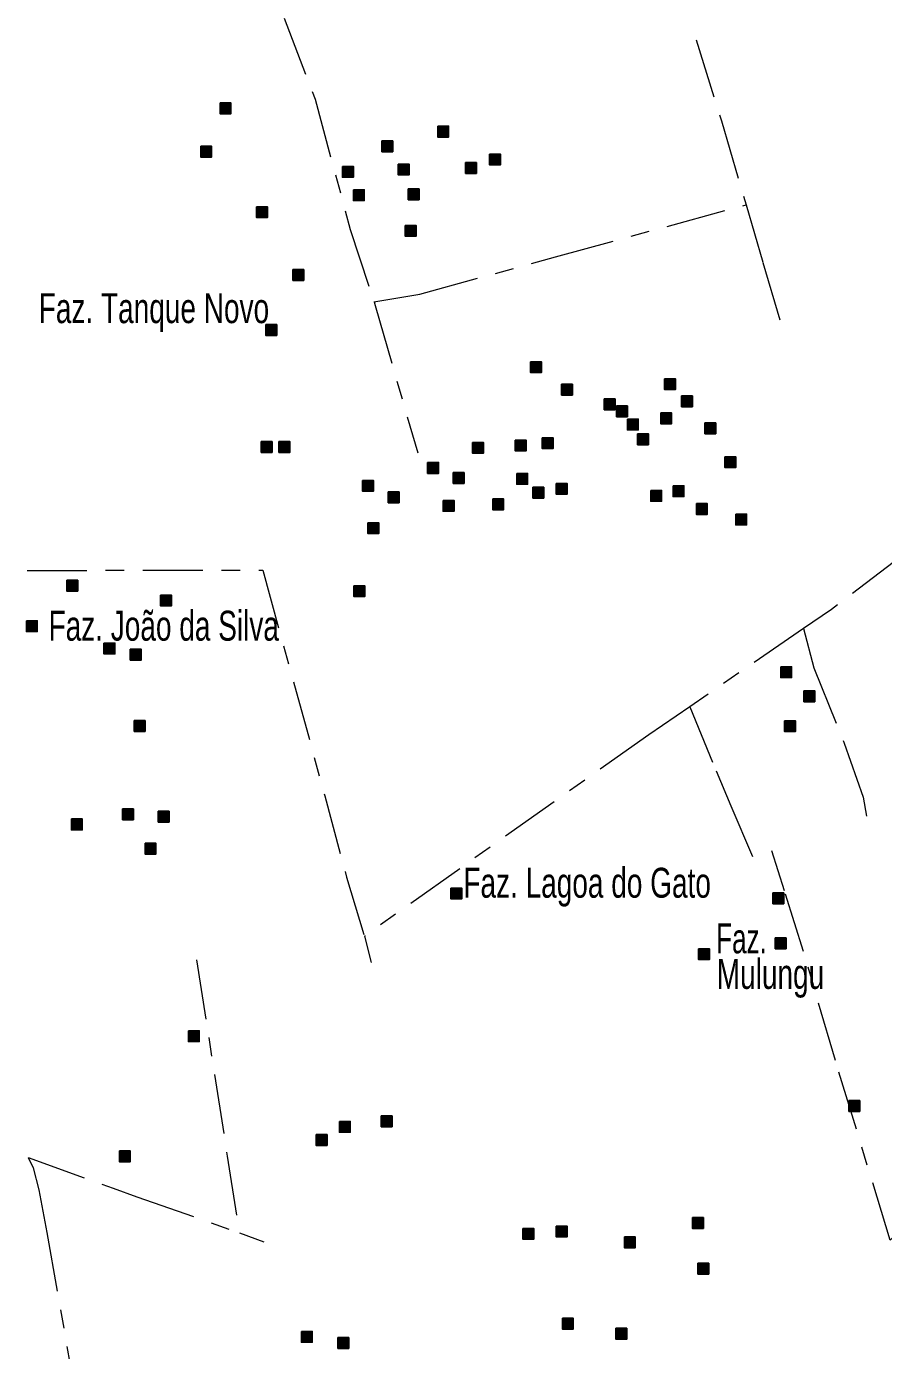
# Model space of a CAD drawing. Extents: x 445.4 to 500, y 8728.7 to 8784.
# Drawn here: x 445.42 to 450, y 8750.72 to 8757.8 of the extents above; entities that cross this region are included whole.
import ezdxf
from ezdxf.enums import TextEntityAlignment as Align

# ---------------------------------------------------------------- set-up
doc = ezdxf.new("R2010")
doc.units = 0
doc.header["$LTSCALE"] = 0.064
doc.linetypes.add('DOT_DASHED', pattern=[7.7, 5, -1.2, 0.3, -1.2])
doc.layers.add('2', color=7, linetype='Continuous', lineweight=25)
doc.layers.add('22', color=7, linetype='DOT_DASHED', lineweight=13)
doc.layers.add('61', color=7, linetype='Continuous')

msp = doc.modelspace()

# ---------------------------------------------------------------- hatches: boundary and pattern name
at = {"layer": '2'}
for points in [[(446.457, 8757.3873), (446.515, 8757.3873), (446.515, 8757.3293), (446.457, 8757.3293)], [(447.6207, 8757.263), (447.6787, 8757.263), (447.6787, 8757.205), (447.6207, 8757.205)], [(446.3534, 8757.1552), (446.4114, 8757.1552), (446.4114, 8757.0972), (446.3534, 8757.0972)], [(447.3225, 8757.1842), (447.3805, 8757.1842), (447.3805, 8757.1262), (447.3225, 8757.1262)], [(447.4095, 8757.0599), (447.4675, 8757.0599), (447.4675, 8757.0019), (447.4095, 8757.0019)], [(447.7698, 8757.0682), (447.8278, 8757.0682), (447.8278, 8757.0102), (447.7698, 8757.0102)], [(447.8981, 8757.1138), (447.9561, 8757.1138), (447.9561, 8757.0558), (447.8981, 8757.0558)], [(447.1113, 8757.0475), (447.1693, 8757.0475), (447.1693, 8756.9895), (447.1113, 8756.9895)], [(447.1693, 8756.9232), (447.2273, 8756.9232), (447.2273, 8756.8652), (447.1693, 8756.8652)], [(447.4633, 8756.9273), (447.5213, 8756.9273), (447.5213, 8756.8693), (447.4633, 8756.8693)], [(446.6516, 8756.832), (446.7096, 8756.832), (446.7096, 8756.774), (446.6516, 8756.774)], [(447.4467, 8756.7326), (447.5047, 8756.7326), (447.5047, 8756.6746), (447.4467, 8756.6746)], [(446.8462, 8756.4964), (446.9042, 8756.4964), (446.9042, 8756.4384), (446.8462, 8756.4384)], [(446.7013, 8756.2022), (446.7593, 8756.2022), (446.7593, 8756.1442), (446.7013, 8756.1442)], [(448.1176, 8756.0032), (448.1756, 8756.0032), (448.1756, 8755.9452), (448.1176, 8755.9452)], [(448.2833, 8755.8831), (448.3413, 8755.8831), (448.3413, 8755.8251), (448.2833, 8755.8251)], [(448.8341, 8755.9121), (448.8921, 8755.9121), (448.8921, 8755.8541), (448.8341, 8755.8541)], [(448.5111, 8755.8043), (448.5691, 8755.8043), (448.5691, 8755.7463), (448.5111, 8755.7463)], [(448.9252, 8755.8209), (448.9832, 8755.8209), (448.9832, 8755.7629), (448.9252, 8755.7629)], [(448.5773, 8755.7671), (448.6353, 8755.7671), (448.6353, 8755.7091), (448.5773, 8755.7091)], [(448.8134, 8755.7298), (448.8714, 8755.7298), (448.8714, 8755.6718), (448.8134, 8755.6718)], [(448.6353, 8755.6966), (448.6933, 8755.6966), (448.6933, 8755.6386), (448.6353, 8755.6386)], [(449.0494, 8755.6759), (449.1074, 8755.6759), (449.1074, 8755.6179), (449.0494, 8755.6179)], [(446.6765, 8755.5764), (446.7345, 8755.5764), (446.7345, 8755.5184), (446.6765, 8755.5184)], [(446.7717, 8755.5764), (446.8297, 8755.5764), (446.8297, 8755.5184), (446.7717, 8755.5184)], [(447.807, 8755.5723), (447.865, 8755.5723), (447.865, 8755.5143), (447.807, 8755.5143)], [(448.0348, 8755.5847), (448.0928, 8755.5847), (448.0928, 8755.5267), (448.0348, 8755.5267)], [(448.1798, 8755.5972), (448.2378, 8755.5972), (448.2378, 8755.5392), (448.1798, 8755.5392)], [(448.6891, 8755.6179), (448.7471, 8755.6179), (448.7471, 8755.5599), (448.6891, 8755.5599)], [(449.1568, 8755.4951), (449.2148, 8755.4951), (449.2148, 8755.4371), (449.1568, 8755.4371)], [(447.5668, 8755.4646), (447.6248, 8755.4646), (447.6248, 8755.4066), (447.5668, 8755.4066)], [(447.219, 8755.3692), (447.277, 8755.3692), (447.277, 8755.3112), (447.219, 8755.3112)], [(447.7035, 8755.4107), (447.7615, 8755.4107), (447.7615, 8755.3527), (447.7035, 8755.3527)], [(448.0431, 8755.4065), (448.1011, 8755.4065), (448.1011, 8755.3485), (448.0431, 8755.3485)], [(448.2543, 8755.3527), (448.3123, 8755.3527), (448.3123, 8755.2947), (448.2543, 8755.2947)], [(447.3556, 8755.3071), (447.4136, 8755.3071), (447.4136, 8755.2491), (447.3556, 8755.2491)], [(448.1301, 8755.332), (448.1881, 8755.332), (448.1881, 8755.274), (448.1301, 8755.274)], [(448.7595, 8755.3154), (448.8175, 8755.3154), (448.8175, 8755.2574), (448.7595, 8755.2574)], [(448.8796, 8755.3402), (448.9376, 8755.3402), (448.9376, 8755.2822), (448.8796, 8755.2822)], [(447.6497, 8755.2615), (447.7077, 8755.2615), (447.7077, 8755.2035), (447.6497, 8755.2035)], [(447.9147, 8755.2698), (447.9727, 8755.2698), (447.9727, 8755.2118), (447.9147, 8755.2118)], [(449.0039, 8755.2449), (449.0619, 8755.2449), (449.0619, 8755.1869), (449.0039, 8755.1869)], [(447.2473, 8755.1427), (447.3053, 8755.1427), (447.3053, 8755.0847), (447.2473, 8755.0847)], [(449.2148, 8755.1885), (449.2728, 8755.1885), (449.2728, 8755.1305), (449.2148, 8755.1305)], [(445.637, 8754.8347), (445.695, 8754.8347), (445.695, 8754.7767), (445.637, 8754.7767)], [(447.172, 8754.8057), (447.23, 8754.8057), (447.23, 8754.7477), (447.172, 8754.7477)], [(446.1381, 8754.756), (446.1961, 8754.756), (446.1961, 8754.698), (446.1381, 8754.698)], [(445.4212, 8754.6186), (445.4792, 8754.6186), (445.4792, 8754.5606), (445.4212, 8754.5606)], [(445.8358, 8754.499), (445.8938, 8754.499), (445.8938, 8754.441), (445.8358, 8754.441)], [(445.9766, 8754.4659), (446.0346, 8754.4659), (446.0346, 8754.4079), (445.9766, 8754.4079)], [(449.455, 8754.3722), (449.513, 8754.3722), (449.513, 8754.3142), (449.455, 8754.3142)], [(449.5793, 8754.2437), (449.6373, 8754.2437), (449.6373, 8754.1857), (449.5793, 8754.1857)], [(445.9973, 8754.0847), (446.0553, 8754.0847), (446.0553, 8754.0267), (445.9973, 8754.0267)], [(449.4757, 8754.0835), (449.5337, 8754.0835), (449.5337, 8754.0255), (449.4757, 8754.0255)], [(445.9352, 8753.6123), (445.9932, 8753.6123), (445.9932, 8753.5543), (445.9352, 8753.5543)], [(446.1257, 8753.5998), (446.1837, 8753.5998), (446.1837, 8753.5418), (446.1257, 8753.5418)], [(445.6618, 8753.5584), (445.7198, 8753.5584), (445.7198, 8753.5004), (445.6618, 8753.5004)], [(446.0553, 8753.4291), (446.1133, 8753.4291), (446.1133, 8753.3711), (446.0553, 8753.3711)], [(447.6911, 8753.1888), (447.7491, 8753.1888), (447.7491, 8753.1308), (447.6911, 8753.1308)], [(449.4136, 8753.163), (449.4716, 8753.163), (449.4716, 8753.105), (449.4136, 8753.105)], [(449.426, 8752.9227), (449.484, 8752.9227), (449.484, 8752.8647), (449.426, 8752.8647)], [(449.016, 8752.8646), (449.074, 8752.8646), (449.074, 8752.8066), (449.016, 8752.8066)], [(446.2872, 8752.4263), (446.3452, 8752.4263), (446.3452, 8752.3683), (446.2872, 8752.3683)], [(449.8195, 8752.0525), (449.8775, 8752.0525), (449.8775, 8751.9945), (449.8195, 8751.9945)], [(447.3184, 8751.9705), (447.3764, 8751.9705), (447.3764, 8751.9125), (447.3184, 8751.9125)], [(447.0947, 8751.9415), (447.1527, 8751.9415), (447.1527, 8751.8835), (447.0947, 8751.8835)], [(446.9705, 8751.871), (447.0285, 8751.871), (447.0285, 8751.813), (446.9705, 8751.813)], [(445.9186, 8751.784), (445.9766, 8751.784), (445.9766, 8751.726), (445.9186, 8751.726)], [(448.9832, 8751.4276), (449.0412, 8751.4276), (449.0412, 8751.3696), (448.9832, 8751.3696)], [(448.0762, 8751.3696), (448.1342, 8751.3696), (448.1342, 8751.3116), (448.0762, 8751.3116)], [(448.2543, 8751.3821), (448.3123, 8751.3821), (448.3123, 8751.3241), (448.2543, 8751.3241)], [(448.6187, 8751.3241), (448.6767, 8751.3241), (448.6767, 8751.2661), (448.6187, 8751.2661)], [(449.0122, 8751.1832), (449.0702, 8751.1832), (449.0702, 8751.1252), (449.0122, 8751.1252)], [(448.2874, 8750.889), (448.3454, 8750.889), (448.3454, 8750.831), (448.2874, 8750.831)], [(448.5732, 8750.8351), (448.6312, 8750.8351), (448.6312, 8750.7771), (448.5732, 8750.7771)], [(446.8918, 8750.8185), (446.9498, 8750.8185), (446.9498, 8750.7605), (446.8918, 8750.7605)], [(447.0864, 8750.7854), (447.1444, 8750.7854), (447.1444, 8750.7274), (447.0864, 8750.7274)]]:
    msp.add_hatch(color=256, dxfattribs=at).paths.add_polyline_path(points)

# ---------------------------------------------------------------- linework, layer by layer
for points in [[(446.457, 8757.3873), (446.515, 8757.3873), (446.515, 8757.3293), (446.457, 8757.3293)], [(447.6207, 8757.263), (447.6787, 8757.263), (447.6787, 8757.205), (447.6207, 8757.205)], [(446.3534, 8757.1552), (446.4114, 8757.1552), (446.4114, 8757.0972), (446.3534, 8757.0972)], [(447.3225, 8757.1842), (447.3805, 8757.1842), (447.3805, 8757.1262), (447.3225, 8757.1262)], [(447.4095, 8757.0599), (447.4675, 8757.0599), (447.4675, 8757.0019), (447.4095, 8757.0019)], [(447.7698, 8757.0682), (447.8278, 8757.0682), (447.8278, 8757.0102), (447.7698, 8757.0102)], [(447.8981, 8757.1138), (447.9561, 8757.1138), (447.9561, 8757.0558), (447.8981, 8757.0558)], [(447.1113, 8757.0475), (447.1693, 8757.0475), (447.1693, 8756.9895), (447.1113, 8756.9895)], [(447.1693, 8756.9232), (447.2273, 8756.9232), (447.2273, 8756.8652), (447.1693, 8756.8652)], [(447.4633, 8756.9273), (447.5213, 8756.9273), (447.5213, 8756.8693), (447.4633, 8756.8693)], [(446.6516, 8756.832), (446.7096, 8756.832), (446.7096, 8756.774), (446.6516, 8756.774)], [(447.4467, 8756.7326), (447.5047, 8756.7326), (447.5047, 8756.6746), (447.4467, 8756.6746)], [(446.8462, 8756.4964), (446.9042, 8756.4964), (446.9042, 8756.4384), (446.8462, 8756.4384)], [(446.7013, 8756.2022), (446.7593, 8756.2022), (446.7593, 8756.1442), (446.7013, 8756.1442)], [(448.1176, 8756.0032), (448.1756, 8756.0032), (448.1756, 8755.9452), (448.1176, 8755.9452)], [(448.2833, 8755.8831), (448.3413, 8755.8831), (448.3413, 8755.8251), (448.2833, 8755.8251)], [(448.8341, 8755.9121), (448.8921, 8755.9121), (448.8921, 8755.8541), (448.8341, 8755.8541)], [(448.5111, 8755.8043), (448.5691, 8755.8043), (448.5691, 8755.7463), (448.5111, 8755.7463)], [(448.9252, 8755.8209), (448.9832, 8755.8209), (448.9832, 8755.7629), (448.9252, 8755.7629)], [(448.5773, 8755.7671), (448.6353, 8755.7671), (448.6353, 8755.7091), (448.5773, 8755.7091)], [(448.8134, 8755.7298), (448.8714, 8755.7298), (448.8714, 8755.6718), (448.8134, 8755.6718)], [(448.6353, 8755.6966), (448.6933, 8755.6966), (448.6933, 8755.6386), (448.6353, 8755.6386)], [(449.0494, 8755.6759), (449.1074, 8755.6759), (449.1074, 8755.6179), (449.0494, 8755.6179)], [(446.6765, 8755.5764), (446.7345, 8755.5764), (446.7345, 8755.5184), (446.6765, 8755.5184)], [(446.7717, 8755.5764), (446.8297, 8755.5764), (446.8297, 8755.5184), (446.7717, 8755.5184)], [(447.807, 8755.5723), (447.865, 8755.5723), (447.865, 8755.5143), (447.807, 8755.5143)], [(448.0348, 8755.5847), (448.0928, 8755.5847), (448.0928, 8755.5267), (448.0348, 8755.5267)], [(448.1798, 8755.5972), (448.2378, 8755.5972), (448.2378, 8755.5392), (448.1798, 8755.5392)], [(448.6891, 8755.6179), (448.7471, 8755.6179), (448.7471, 8755.5599), (448.6891, 8755.5599)], [(449.1568, 8755.4951), (449.2148, 8755.4951), (449.2148, 8755.4371), (449.1568, 8755.4371)], [(447.5668, 8755.4646), (447.6248, 8755.4646), (447.6248, 8755.4066), (447.5668, 8755.4066)], [(447.219, 8755.3692), (447.277, 8755.3692), (447.277, 8755.3112), (447.219, 8755.3112)], [(447.7035, 8755.4107), (447.7615, 8755.4107), (447.7615, 8755.3527), (447.7035, 8755.3527)], [(448.0431, 8755.4065), (448.1011, 8755.4065), (448.1011, 8755.3485), (448.0431, 8755.3485)], [(448.2543, 8755.3527), (448.3123, 8755.3527), (448.3123, 8755.2947), (448.2543, 8755.2947)], [(447.3556, 8755.3071), (447.4136, 8755.3071), (447.4136, 8755.2491), (447.3556, 8755.2491)], [(448.1301, 8755.332), (448.1881, 8755.332), (448.1881, 8755.274), (448.1301, 8755.274)], [(448.7595, 8755.3154), (448.8175, 8755.3154), (448.8175, 8755.2574), (448.7595, 8755.2574)], [(448.8796, 8755.3402), (448.9376, 8755.3402), (448.9376, 8755.2822), (448.8796, 8755.2822)], [(447.6497, 8755.2615), (447.7077, 8755.2615), (447.7077, 8755.2035), (447.6497, 8755.2035)], [(447.9147, 8755.2698), (447.9727, 8755.2698), (447.9727, 8755.2118), (447.9147, 8755.2118)], [(449.0039, 8755.2449), (449.0619, 8755.2449), (449.0619, 8755.1869), (449.0039, 8755.1869)], [(447.2473, 8755.1427), (447.3053, 8755.1427), (447.3053, 8755.0847), (447.2473, 8755.0847)], [(449.2148, 8755.1885), (449.2728, 8755.1885), (449.2728, 8755.1305), (449.2148, 8755.1305)], [(445.637, 8754.8347), (445.695, 8754.8347), (445.695, 8754.7767), (445.637, 8754.7767)], [(447.172, 8754.8057), (447.23, 8754.8057), (447.23, 8754.7477), (447.172, 8754.7477)], [(446.1381, 8754.756), (446.1961, 8754.756), (446.1961, 8754.698), (446.1381, 8754.698)], [(445.4212, 8754.6186), (445.4792, 8754.6186), (445.4792, 8754.5606), (445.4212, 8754.5606)], [(445.8358, 8754.499), (445.8938, 8754.499), (445.8938, 8754.441), (445.8358, 8754.441)], [(445.9766, 8754.4659), (446.0346, 8754.4659), (446.0346, 8754.4079), (445.9766, 8754.4079)], [(449.455, 8754.3722), (449.513, 8754.3722), (449.513, 8754.3142), (449.455, 8754.3142)], [(449.5793, 8754.2437), (449.6373, 8754.2437), (449.6373, 8754.1857), (449.5793, 8754.1857)], [(445.9973, 8754.0847), (446.0553, 8754.0847), (446.0553, 8754.0267), (445.9973, 8754.0267)], [(449.4757, 8754.0835), (449.5337, 8754.0835), (449.5337, 8754.0255), (449.4757, 8754.0255)], [(445.9352, 8753.6123), (445.9932, 8753.6123), (445.9932, 8753.5543), (445.9352, 8753.5543)], [(446.1257, 8753.5998), (446.1837, 8753.5998), (446.1837, 8753.5418), (446.1257, 8753.5418)], [(445.6618, 8753.5584), (445.7198, 8753.5584), (445.7198, 8753.5004), (445.6618, 8753.5004)], [(446.0553, 8753.4291), (446.1133, 8753.4291), (446.1133, 8753.3711), (446.0553, 8753.3711)], [(447.6911, 8753.1888), (447.7491, 8753.1888), (447.7491, 8753.1308), (447.6911, 8753.1308)], [(449.4136, 8753.163), (449.4716, 8753.163), (449.4716, 8753.105), (449.4136, 8753.105)], [(449.426, 8752.9227), (449.484, 8752.9227), (449.484, 8752.8647), (449.426, 8752.8647)], [(449.016, 8752.8646), (449.074, 8752.8646), (449.074, 8752.8066), (449.016, 8752.8066)], [(446.2872, 8752.4263), (446.3452, 8752.4263), (446.3452, 8752.3683), (446.2872, 8752.3683)], [(449.8195, 8752.0525), (449.8775, 8752.0525), (449.8775, 8751.9945), (449.8195, 8751.9945)], [(447.3184, 8751.9705), (447.3764, 8751.9705), (447.3764, 8751.9125), (447.3184, 8751.9125)], [(447.0947, 8751.9415), (447.1527, 8751.9415), (447.1527, 8751.8835), (447.0947, 8751.8835)], [(446.9705, 8751.871), (447.0285, 8751.871), (447.0285, 8751.813), (446.9705, 8751.813)], [(445.9186, 8751.784), (445.9766, 8751.784), (445.9766, 8751.726), (445.9186, 8751.726)], [(448.9832, 8751.4276), (449.0412, 8751.4276), (449.0412, 8751.3696), (448.9832, 8751.3696)], [(448.0762, 8751.3696), (448.1342, 8751.3696), (448.1342, 8751.3116), (448.0762, 8751.3116)], [(448.2543, 8751.3821), (448.3123, 8751.3821), (448.3123, 8751.3241), (448.2543, 8751.3241)], [(448.6187, 8751.3241), (448.6767, 8751.3241), (448.6767, 8751.2661), (448.6187, 8751.2661)], [(449.0122, 8751.1832), (449.0702, 8751.1832), (449.0702, 8751.1252), (449.0122, 8751.1252)], [(448.2874, 8750.889), (448.3454, 8750.889), (448.3454, 8750.831), (448.2874, 8750.831)], [(448.5732, 8750.8351), (448.6312, 8750.8351), (448.6312, 8750.7771), (448.5732, 8750.7771)], [(446.8918, 8750.8185), (446.9498, 8750.8185), (446.9498, 8750.7605), (446.8918, 8750.7605)], [(447.0864, 8750.7854), (447.1444, 8750.7854), (447.1444, 8750.7274), (447.0864, 8750.7274)]]:
    msp.add_lwpolyline(points, close=True, dxfattribs=at)
at = {"layer": '22'}
for points in [[(446.7989, 8757.8396), (446.9645, 8757.4079), (447.1528, 8756.711), (447.2799, 8756.3238)], [(449.002, 8757.7249), (449.1381, 8757.2917), (449.2696, 8756.8423)], [(447.2798, 8756.3238), (447.5245, 8756.3648), (448.25, 8756.5639), (449.2696, 8756.8423)], [(449.2696, 8756.8423), (449.3597, 8756.5343), (449.4726, 8756.1499)], [(447.2799, 8756.3238), (447.2864, 8756.3039), (447.5136, 8755.5154)], [(453.2508, 8755.9296), (451.7986, 8755.3634), (451.2846, 8755.1612), (451.1911, 8755.1223), (450.9341, 8755.0912), (450.1864, 8755.0212), (450.093, 8754.9589), (449.7269, 8754.6789), (449.5777, 8754.5766), (448.9686, 8754.1589)], [(445.4242, 8754.8875), (446.6844, 8754.8891), (447.0167, 8753.6827), (447.1336, 8753.2471), (447.2284, 8752.9314), (447.2651, 8752.7905)], [(449.5777, 8754.5766), (449.6316, 8754.3675), (449.7951, 8753.9631), (449.8964, 8753.6753), (449.9144, 8753.5741)], [(448.9686, 8754.1589), (448.7501, 8754.009), (447.2284, 8752.9314)], [(448.9686, 8754.1589), (449.1097, 8753.8153), (449.1876, 8753.6286), (449.304, 8753.3578)], [(451.2183, 8753.9994), (451.5566, 8752.9863), (450.9959, 8752.3641), (450.0963, 8751.3607), (450.0406, 8751.3064), (449.7479, 8752.2671), (449.5766, 8752.8504), (449.475, 8753.1737), (449.4067, 8753.3884)], [(446.3312, 8752.8049), (446.4951, 8751.7558), (446.5598, 8751.3462)], [(445.4295, 8751.7489), (445.4572, 8751.6937), (445.4869, 8751.5759), (445.5307, 8751.3482), (445.6902, 8750.4356), (445.712, 8750.3115), (445.7243, 8750.224)], [(445.4295, 8751.7482), (445.8845, 8751.5845), (446.0123, 8751.538), (446.5598, 8751.3462), (446.6911, 8751.2983)]]:
    msp.add_lwpolyline(points, dxfattribs=at)

# ---------------------------------------------------------------- texts
at = {"layer": '61', "width": 0.7}
msp.add_text('Faz. Tanque Novo', height=0.16, dxfattribs=at).set_placement((446.719, 8756.2099), align=Align.RIGHT)
at = {"layer": '61'}
for s, width, p in [('Faz. João da Silva', 0.7, (445.5392, 8754.5119)), ('Faz. Lagoa do Gato', 0.7, (447.7578, 8753.1377)), (' Faz.', 0.65, (449.0713, 8752.8402)), (' Mulungu', 0.7, (449.0713, 8752.6502))]:
    msp.add_text(s, height=0.16, dxfattribs=dict(at, width=width)).set_placement(p)

doc.saveas('drawing.dxf')
